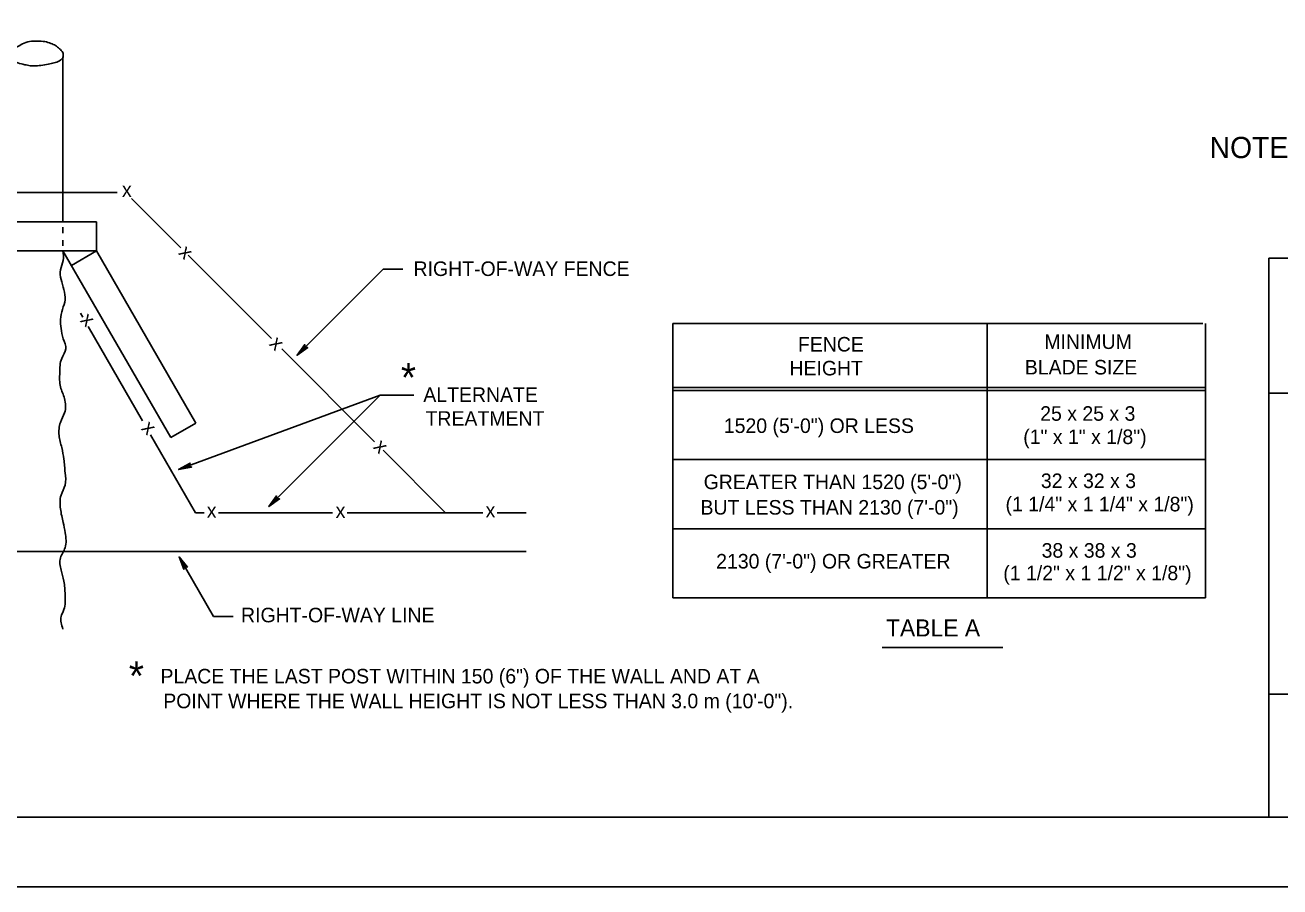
# Model space of a CAD drawing. Extents: x 13 to 918, y -903 to 879.
# Drawn here: x 370 to 639.6, y -903.1 to -718 of the extents above; entities that cross this region are included whole.
import ezdxf

# ---------------------------------------------------------------- set-up
doc = ezdxf.new("R2010")
doc.units = 0
for name, color, linetype in [('1', 7, 'Continuous'), ('2', 7, 'Continuous'), ('3', 7, 'Continuous'), ('40', 7, 'Continuous'), ('PLT-BNDY', 7, 'Continuous')]:
    doc.layers.add(name, color=color, linetype=linetype)

msp = doc.modelspace()

# ---------------------------------------------------------------- linework, layer by layer
at = {"layer": '1'}
for p, q in [((378.15025, -724.81825), (378.15025, -760.235)), ((385.367, -760.235), (385.367, -766.485)), ((378.15025, -761.40525), (378.15025, -762.69725)), ((378.15025, -764.23175), (378.15025, -765.44325)), ((446.9295, -770.43275), (451.146, -770.43275)), ((509.18825, -782.0615), (509.18825, -841.03225)), ((509.18825, -782.0615), (623.052, -782.0615)), ((576.7025, -782.0615), (576.7025, -841.03225)), ((623.63525, -782.0615), (623.63525, -841.03225)), ((446.32325, -797.47875), (453.5295, -797.47875)), ((509.18825, -795.84875), (623.63525, -795.84875)), ((509.18825, -796.46775), (623.63525, -796.46775)), ((623.63525, -811.3115), (509.18825, -811.3115)), ((577.54975, -826.1885), (509.18825, -826.1885)), ((623.63525, -826.1885), (577.54975, -826.1885)), ((509.18825, -841.03225), (623.63525, -841.03225)), ((410.49825, -845.00775), (414.71475, -845.00775))]:
    msp.add_line(p, q, dxfattribs=at)
msp.add_lwpolyline([(837.2505, -888.06975), (837.2505, -324.06975), (51.2505, -324.06975), (51.2505, -888.06975), (837.2505, -888.06975), (837.2505, -861.71075), (637.2505, -861.71075), (637.2505, -797.03325), (837.2505, -797.03325), (837.2505, -768.06975), (637.2505, -768.06975), (637.2505, -888.06975), (716.052, -888.06975), (716.052, -861.71075), (716.052, -888.06975), (793.052, -888.06975), (793.052, -861.71075), (793.052, -874.02725), (837.2505, -874.02725)], dxfattribs=at)
at = {"layer": '2'}
msp.add_spline([(353.1545, -724.82025), (353.71075, -724.012), (354.244, -723.1725), (355.27325, -722.25575), (356.8045, -721.68075), (359.667, -721.64525), (361.2315, -722.10375), (362.37525, -722.82875), (363.59825, -723.47875), (364.442, -723.9725), (365.16475, -724.3975), (365.66075, -724.82025), (366.619, -725.462), (367.6085, -725.8475), (369.25225, -726.34525), (370.244, -726.5745), (371.4295, -726.76625), (372.3045, -726.76625), (373.796, -726.6475), (375.36475, -726.34525), (376.51075, -726.07875), (377.694, -725.5015), (378.169, -724.82025), (378.11075, -723.937), (377.38575, -723.09525), (376.546, -722.40575), (375.5545, -721.9475), (374.2545, -721.56825), (372.68975, -721.4515), (371.38975, -721.49525), (369.78575, -721.91), (368.60225, -722.5225), (367.5335, -723.09525), (366.692, -723.82025), (365.66075, -724.82025)], degree=3, dxfattribs=at)
at = {"layer": '3'}
for p, q in [((340.169, -753.985), (389.7795, -753.985)), ((392.90025, -755.26825), (403.5045, -765.87025)), ((345.367, -760.235), (385.367, -760.235)), ((345.367, -766.485), (385.367, -766.485)), ((401.3085, -806.59525), (378.15025, -766.485)), ((385.367, -766.485), (379.9545, -769.61)), ((406.721, -803.47025), (385.367, -766.485)), ((405.03575, -767.4015), (422.93775, -785.30375)), ((428.45025, -788.912), (446.9295, -770.43275)), ((382.40025, -780.7245), (381.92525, -779.9015)), ((395.2545, -802.987), (383.5585, -782.72875)), ((425.18975, -787.55575), (445.117, -807.485)), ((403.0085, -813.45375), (446.32325, -797.47875)), ((422.396, -821.40575), (446.32325, -797.47875)), ((406.6565, -822.735), (396.97525, -805.96825)), ((406.721, -803.47025), (401.3085, -806.59525)), ((446.921, -809.287), (460.367, -822.735)), ((406.6565, -822.735), (408.4835, -822.735)), ((411.54825, -822.735), (436.06275, -822.735)), ((439.23975, -822.735), (460.367, -822.735)), ((460.367, -822.735), (468.371, -822.735)), ((471.43575, -822.735), (477.67525, -822.735)), ((61.192, -831.06825), (477.67525, -831.06825)), ((410.49825, -845.00775), (403.117, -832.2225)), ((554.1335, -851.685), (580.094, -851.685))]:
    msp.add_line(p, q, dxfattribs=at)
for points in [[(430.5585, -787.2745), (430.35225, -787.20775), (428.45025, -788.912), (430.5585, -787.2745), (430.73575, -787.26), (428.45025, -788.912), (430.16275, -787.02025), (430.094, -786.82025), (428.45025, -788.912), (430.1065, -786.63075), (430.094, -786.82025)], [(405.6085, -812.8495), (405.45025, -812.70375), (403.0085, -813.45375), (405.6085, -812.8495), (405.77725, -812.912), (403.0085, -813.45375), (405.3565, -812.45375), (405.37725, -812.24325), (403.0085, -813.45375), (405.469, -812.0745), (405.37725, -812.24325)], [(424.5045, -819.76825), (424.29825, -819.7015), (422.396, -821.40575), (424.5045, -819.76825), (424.6815, -819.75375), (422.396, -821.40575), (424.1085, -819.514), (424.03975, -819.314), (422.396, -821.40575), (424.05225, -819.1245), (424.03975, -819.314)], [(404.15225, -834.68275), (404.269, -834.5015), (403.117, -832.2225), (404.15225, -834.68275), (404.121, -834.85775), (403.117, -832.2225), (404.50025, -834.36625), (404.71075, -834.3515), (403.117, -832.2225), (404.892, -834.412), (404.71075, -834.3515)]]:
    msp.add_lwpolyline(points, dxfattribs=at)
msp.add_spline([(378.15025, -766.485), (378.192, -768.53275), (377.61275, -770.57025), (377.744, -772.6265), (378.342, -774.812), (378.62325, -777.01625), (378.044, -779.05375), (377.61275, -781.239), (377.744, -783.14525), (378.192, -785.3515), (378.771, -787.537), (377.894, -789.59325), (377.46475, -792.65575), (377.61275, -795.72025), (378.492, -798.20575), (378.492, -801.289), (377.61275, -803.3265), (377.31475, -806.11), (377.894, -808.74525), (378.342, -811.23075), (378.62325, -814.14525), (378.62325, -816.78075), (377.744, -818.96625), (377.61275, -821.8995), (378.192, -824.814), (378.62325, -827.02025), (378.62325, -830.23275), (377.61275, -832.42025), (377.744, -835.05375), (378.342, -837.389), (378.62325, -840.3245), (378.342, -843.537), (377.744, -844.99525), (378.15025, -847.735)], degree=3, dxfattribs=at)
at = {"layer": 'PLT-BNDY'}
msp.add_lwpolyline([(13.2505, -309.06975), (854.2505, -309.06975), (854.2505, -903.06975), (13.2505, -903.06975)], close=True, dxfattribs=at)

# ---------------------------------------------------------------- texts
at = {"layer": '3'}
for s, height, p in [('x', 3.125, (390.8315, -754.90575)), ('RIGHT-OF-WAY FENCE', 3.1249995, (453.469, -771.89125)), ('MINIMUM', 3.124999, (589.001, -787.5645)), ('FENCE', 3.124999, (536.06, -788.1125)), ('BLADE SIZE', 3.124999, (584.80575, -793.04225)), ('*', 6.25, (450.75025, -796.80575)), ('HEIGHT', 3.124999, (534.2345, -793.2435)), ('ALTERNATE', 3.124999, (455.57525, -798.92875)), ('25 x 25 x 3', 3.1249995, (588.113, -802.979)), ('TREATMENT', 3.124999, (456.05025, -804.04525)), ('1520 (5\'-0") OR LESS', 3.1249995, (520.13925, -805.60225)), ('(1" x 1" x 1/8")', 3.1249995, (584.464, -807.98575)), ('GREATER THAN 1520 (5\'-0")', 3.1249995, (515.81, -817.66625)), ('32 x 32 x 3', 3.1249995, (588.2495, -817.42625)), ('(1 1/4" x 1 1/4" x 1/8")', 3.1249995, (580.66, -822.43375)), ('x', 3.125, (409.05025, -823.81625)), ('x', 3.125, (436.744, -823.835)), ('x', 3.125, (468.9565, -823.74125)), ('BUT LESS THAN 2130 (7\'-0")', 3.1249995, (515.1265, -823.12725)), ('38 x 38 x 3', 3.1249995, (588.4135, -832.38125)), ('2130 (7\'-0") OR GREATER', 3.1249995, (518.49325, -834.70325)), ('(1 1/2" x 1 1/2" x 1/8")', 3.1249995, (580.178, -837.227)), ('RIGHT-OF-WAY LINE', 3.1249995, (416.41275, -846.25775)), ('TABLE A', 3.677087, (554.97925, -849.30325)), ('*', 6.25, (392.30225, -860.87875)), ('PLACE THE LAST POST WITHIN 150 (6") OF THE WALL AND AT A', 3.1249995, (399.1045, -859.38275)), ('POINT WHERE THE WALL HEIGHT IS NOT LESS THAN 3.0 m (10\'-0").', 3.1249995, (399.70025, -864.71))]:
    msp.add_text(s, height=height, dxfattribs=at).set_placement(p)
for p in [(402.794, -767.0725), (381.6795, -781.55575), (422.319, -786.61625), (394.8335, -804.74325), (444.667, -808.74125)]:
    msp.add_text('x', height=3.125, rotation=315, dxfattribs=at).set_placement(p)
at = {"layer": '40'}
msp.add_text('NOTE: EITHER ALL METRIC OR ALL ENGLISH VALUES', height=4.558749, dxfattribs=at).set_placement((624.4995, -746.581))

doc.saveas('drawing.dxf')
